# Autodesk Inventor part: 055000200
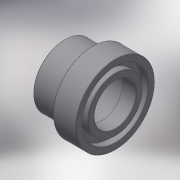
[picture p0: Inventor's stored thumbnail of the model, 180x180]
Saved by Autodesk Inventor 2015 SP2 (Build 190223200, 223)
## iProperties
Created: 2017-10
Part Number: 055000200
Material: Generic
Description: PLASSON FLANGE AD.+O-RING-CE 200
Document SubType Name: Modeling
Designer: KIM
Density: 1 g/cm^3
Appearance: Default
Author: KIM
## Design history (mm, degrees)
derived "055000.ipt"
feature "Solid1::055000.ipt"
tag "TaggingFeature1"
body "Solid1"
other parameters: "d0" = 119, "d1" = 228, "d4" = 23, "d5" = 106, "d6" = 254, "d8" = 6.9, "d11" = 2, "d12" = 6.9, "d15" = 11.1, "E_" = 228, "E_1" = 254, "l_" = 106, "B_" = 23, "H_" = 119, "d14" = 37
